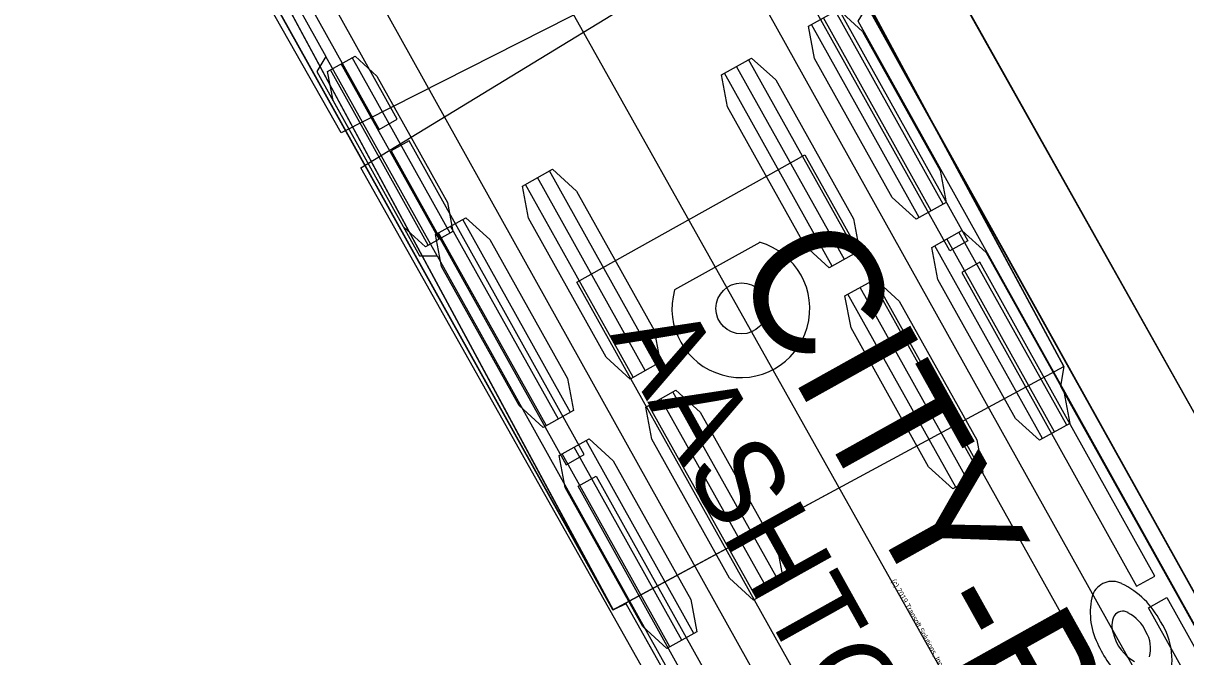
# Model space of a CAD drawing. Extents: x 1639988 to 1641860, y 841974 to 844187.
# Drawn here: x 1640568.27 to 1640587.55, y 843385.15 to 843395.66 of the extents above; entities that cross this region are included whole.
import ezdxf

# ---------------------------------------------------------------- set-up
doc = ezdxf.new("R2010")
doc.units = 0
for name, color, linetype in [('Scratch_Level_1', 7, 'Continuous'), ('Scratch_Level_2', 7, 'Continuous'), ('Scratch_Level_3', 7, 'Continuous'), ('Scratch_Level_4', 7, 'Continuous'), ('Scratch_Level_5', 7, 'Continuous'), ('Scratch_Level_6', 7, 'Continuous')]:
    doc.layers.add(name, color=color, linetype=linetype)

msp = doc.modelspace()

# ---------------------------------------------------------------- linework, layer by layer
at = {"layer": 'Scratch_Level_1'}
for p, q in [((1640561.019, 843424.987), (1640589.875, 843373.561)), ((1640583.328, 843392.545), (1640581.54, 843395.746)), ((1640583.528, 843392.657), (1640581.74, 843395.858)), ((1640583.128, 843392.433), (1640581.34, 843395.635)), ((1640581.888, 843391.741), (1640580.1, 843394.942)), ((1640582.088, 843391.852), (1640580.3, 843395.054)), ((1640581.688, 843391.629), (1640579.9, 843394.83)), ((1640578.785, 843390.007), (1640576.997, 843393.209)), ((1640578.585, 843389.896), (1640576.797, 843393.097)), ((1640578.385, 843389.784), (1640576.597, 843392.985)), ((1640577.144, 843389.091), (1640575.356, 843392.292)), ((1640577.344, 843389.203), (1640575.556, 843392.404)), ((1640576.944, 843388.979), (1640575.156, 843392.181)), ((1640585.376, 843388.878), (1640583.588, 843392.08)), ((1640585.576, 843388.99), (1640583.788, 843392.191)), ((1640580.483, 843392.023), (1640579.072, 843391.235)), ((1640585.176, 843388.767), (1640583.388, 843391.968)), ((1640583.936, 843388.074), (1640582.148, 843391.275)), ((1640584.136, 843388.186), (1640582.348, 843391.387)), ((1640583.736, 843387.962), (1640581.948, 843391.163)), ((1640580.833, 843386.341), (1640579.045, 843389.542)), ((1640580.633, 843386.229), (1640578.845, 843389.43)), ((1640580.433, 843386.117), (1640578.645, 843389.318)), ((1640579.192, 843385.424), (1640577.404, 843388.626)), ((1640579.392, 843385.536), (1640577.604, 843388.737)), ((1640578.992, 843385.313), (1640577.204, 843388.514))]:
    msp.add_line(p, q, dxfattribs=at)
for points in [[(1640557.303, 843442.315), (1640585.531, 843389.964), (1640585.474, 843389.635), (1640595.318, 843372.019), (1640588.329, 843368.125), (1640578.269, 843386.026), (1640578.051, 843385.927), (1640567.623, 843404.617), (1640561.145, 843416.327), (1640558.494, 843420.979), (1640555.889, 843425.657), (1640554.452, 843428.305), (1640561.33, 843432.392), (1640554.136, 843428.893), (1640551.649, 843433.615), (1640549.228, 843438.375), (1640546.875, 843443.171)], [(1640629.14, 843315.333), (1640571.712, 843417.686), (1640569.11, 843422.364), (1640566.534, 843427.059), (1640563.994, 843431.777), (1640560.226, 843438.882)], [(1640552.934, 843432.517), (1640552.915, 843432.507), (1640552.949, 843432.445), (1640555.639, 843427.457), (1640578.051, 843385.927), (1640581.791, 843387.945), (1640585.531, 843389.964), (1640563.12, 843431.494), (1640560.428, 843436.481), (1640560.394, 843436.543), (1640560.375, 843436.533)], [(1640582.021, 843381.774), (1640582.62, 843382.108), (1640582.505, 843382.316), (1640577.452, 843391.363), (1640579.342, 843392.419), (1640581.232, 843393.475), (1640586.285, 843384.428), (1640586.402, 843384.221), (1640587.001, 843384.555)]]:
    msp.add_lwpolyline(points, dxfattribs=at)
for points in [[(1640583.578, 843392.685), (1640583.078, 843392.406), (1640582.678, 843392.77), (1640581.39, 843395.075), (1640581.291, 843395.607), (1640581.79, 843395.886), (1640582.191, 843395.522), (1640583.478, 843393.217)], [(1640582.137, 843391.88), (1640581.638, 843391.601), (1640581.237, 843391.965), (1640579.95, 843394.27), (1640579.85, 843394.802), (1640580.349, 843395.081), (1640580.75, 843394.717), (1640582.037, 843392.412)], [(1640578.834, 843390.035), (1640578.335, 843389.756), (1640577.934, 843390.12), (1640576.647, 843392.425), (1640576.547, 843392.957), (1640577.046, 843393.236), (1640577.447, 843392.872), (1640578.734, 843390.567)], [(1640577.394, 843389.231), (1640576.894, 843388.952), (1640576.494, 843389.316), (1640575.206, 843391.621), (1640575.106, 843392.153), (1640575.606, 843392.432), (1640576.007, 843392.068), (1640577.294, 843389.763)], [(1640585.626, 843389.018), (1640585.127, 843388.739), (1640584.726, 843389.103), (1640583.438, 843391.408), (1640583.339, 843391.94), (1640583.838, 843392.219), (1640584.239, 843391.855), (1640585.526, 843389.55)], [(1640584.185, 843388.213), (1640583.686, 843387.934), (1640583.285, 843388.298), (1640581.998, 843390.603), (1640581.898, 843391.135), (1640582.397, 843391.414), (1640582.798, 843391.05), (1640584.086, 843388.745)], [(1640580.882, 843386.368), (1640580.383, 843386.089), (1640579.982, 843386.454), (1640578.695, 843388.758), (1640578.595, 843389.291), (1640579.094, 843389.57), (1640579.495, 843389.205), (1640580.782, 843386.901)], [(1640579.442, 843385.564), (1640578.942, 843385.285), (1640578.542, 843385.649), (1640577.254, 843387.954), (1640577.154, 843388.486), (1640577.654, 843388.765), (1640578.055, 843388.401), (1640579.342, 843386.096)]]:
    msp.add_lwpolyline(points, close=True, dxfattribs=at)
msp.add_circle((1640580.182, 843390.927), 0.424, dxfattribs=at)
for centre, radius, start, end in [((1640580.171, 843390.924), 1.143, 164.1847, 74.1847), ((1640586.331, 843386.054), 0.346, 62.5774, 159.5905), ((1640585.873, 843385.086), 1.416, 27.1129, 64.1808), ((1640587.103, 843385.88), 1.136, 164.9487, 206.4695), ((1640586.506, 843385.732), 0.172, 59.4864, 146.6369), ((1640586.284, 843385.292), 0.664, 24.0886, 62.3103), ((1640586.686, 843385.665), 0.362, 153.4813, 202.5223), ((1640586.187, 843385.103), 1.136, 338.8147, 33.606), ((1640587.06, 843385.707), 0.732, 194.3586, 240.593), ((1640586.445, 843385.291), 0.522, 344.1901, 31.3542), ((1640587.679, 843386.05), 1.73, 203.0114, 227.8099)]:
    msp.add_arc(centre, radius, start, end, dxfattribs=at)
at = {"layer": 'Scratch_Level_2'}
for p, q in [((1640561.019, 843424.987), (1640589.875, 843373.561)), ((1640583.328, 843392.545), (1640581.54, 843395.746)), ((1640583.528, 843392.657), (1640581.74, 843395.858)), ((1640583.128, 843392.433), (1640581.34, 843395.635)), ((1640581.888, 843391.741), (1640580.1, 843394.942)), ((1640582.088, 843391.852), (1640580.3, 843395.054)), ((1640581.688, 843391.629), (1640579.9, 843394.83)), ((1640578.785, 843390.007), (1640576.997, 843393.209)), ((1640578.585, 843389.896), (1640576.797, 843393.097)), ((1640578.385, 843389.784), (1640576.597, 843392.985)), ((1640577.144, 843389.091), (1640575.356, 843392.292)), ((1640577.344, 843389.203), (1640575.556, 843392.404)), ((1640576.944, 843388.979), (1640575.156, 843392.181)), ((1640585.376, 843388.878), (1640583.588, 843392.08)), ((1640585.576, 843388.99), (1640583.788, 843392.191)), ((1640580.483, 843392.023), (1640579.072, 843391.235)), ((1640585.176, 843388.767), (1640583.388, 843391.968)), ((1640583.936, 843388.074), (1640582.148, 843391.275)), ((1640584.136, 843388.186), (1640582.348, 843391.387)), ((1640583.736, 843387.962), (1640581.948, 843391.163)), ((1640580.833, 843386.341), (1640579.045, 843389.542)), ((1640580.633, 843386.229), (1640578.845, 843389.43)), ((1640580.433, 843386.117), (1640578.645, 843389.318)), ((1640579.192, 843385.424), (1640577.404, 843388.626)), ((1640579.392, 843385.536), (1640577.604, 843388.737)), ((1640578.992, 843385.313), (1640577.204, 843388.514))]:
    msp.add_line(p, q, dxfattribs=at)
for points in [[(1640557.951, 843441.151), (1640585.531, 843389.961), (1640585.474, 843389.635), (1640595.318, 843372.019), (1640588.329, 843368.125), (1640578.268, 843386.026), (1640578.049, 843385.928), (1640567.621, 843404.618), (1640561.144, 843416.329), (1640558.493, 843420.981), (1640555.888, 843425.659), (1640554.451, 843428.306), (1640561.331, 843432.39), (1640554.135, 843428.895), (1640551.648, 843433.617), (1640549.227, 843438.377), (1640546.874, 843443.173)], [(1640629.144, 843315.327), (1640571.712, 843417.686), (1640569.11, 843422.364), (1640566.534, 843427.059), (1640563.994, 843431.777), (1640560.226, 843438.882)], [(1640552.951, 843432.529), (1640552.932, 843432.518), (1640552.966, 843432.456), (1640555.654, 843427.467), (1640578.049, 843385.928), (1640581.79, 843387.945), (1640585.531, 843389.961), (1640563.136, 843431.501), (1640560.446, 843436.489), (1640560.413, 843436.551), (1640560.394, 843436.541)], [(1640582.021, 843381.774), (1640582.62, 843382.108), (1640582.505, 843382.316), (1640577.452, 843391.363), (1640579.342, 843392.419), (1640581.232, 843393.475), (1640586.285, 843384.428), (1640586.402, 843384.221), (1640587.001, 843384.555)]]:
    msp.add_lwpolyline(points, dxfattribs=at)
for points in [[(1640583.578, 843392.685), (1640583.078, 843392.406), (1640582.678, 843392.77), (1640581.39, 843395.075), (1640581.291, 843395.607), (1640581.79, 843395.886), (1640582.191, 843395.522), (1640583.478, 843393.217)], [(1640582.137, 843391.88), (1640581.638, 843391.601), (1640581.237, 843391.965), (1640579.95, 843394.27), (1640579.85, 843394.802), (1640580.349, 843395.081), (1640580.75, 843394.717), (1640582.037, 843392.412)], [(1640578.834, 843390.035), (1640578.335, 843389.756), (1640577.934, 843390.12), (1640576.647, 843392.425), (1640576.547, 843392.957), (1640577.046, 843393.236), (1640577.447, 843392.872), (1640578.734, 843390.567)], [(1640577.394, 843389.231), (1640576.894, 843388.952), (1640576.494, 843389.316), (1640575.206, 843391.621), (1640575.106, 843392.153), (1640575.606, 843392.432), (1640576.007, 843392.068), (1640577.294, 843389.763)], [(1640585.626, 843389.018), (1640585.127, 843388.739), (1640584.726, 843389.103), (1640583.438, 843391.408), (1640583.339, 843391.94), (1640583.838, 843392.219), (1640584.239, 843391.855), (1640585.526, 843389.55)], [(1640584.185, 843388.213), (1640583.686, 843387.934), (1640583.285, 843388.298), (1640581.998, 843390.603), (1640581.898, 843391.135), (1640582.397, 843391.414), (1640582.798, 843391.05), (1640584.086, 843388.745)], [(1640580.882, 843386.368), (1640580.383, 843386.089), (1640579.982, 843386.454), (1640578.695, 843388.758), (1640578.595, 843389.291), (1640579.094, 843389.57), (1640579.495, 843389.205), (1640580.782, 843386.901)], [(1640579.442, 843385.564), (1640578.942, 843385.285), (1640578.542, 843385.649), (1640577.254, 843387.954), (1640577.154, 843388.486), (1640577.654, 843388.765), (1640578.055, 843388.401), (1640579.342, 843386.096)]]:
    msp.add_lwpolyline(points, close=True, dxfattribs=at)
msp.add_circle((1640580.182, 843390.927), 0.424, dxfattribs=at)
for centre, radius, start, end in [((1640580.171, 843390.924), 1.143, 164.1847, 74.1847), ((1640586.331, 843386.054), 0.346, 62.5774, 159.5905), ((1640585.873, 843385.086), 1.416, 27.1129, 64.1808), ((1640587.103, 843385.88), 1.136, 164.9487, 206.4695), ((1640586.506, 843385.732), 0.172, 59.4864, 146.6369), ((1640586.284, 843385.292), 0.664, 24.0886, 62.3103), ((1640586.686, 843385.665), 0.362, 153.4813, 202.5223), ((1640586.187, 843385.103), 1.136, 338.8147, 33.606), ((1640587.06, 843385.707), 0.732, 194.3586, 240.593), ((1640586.445, 843385.291), 0.522, 344.1901, 31.3542), ((1640587.679, 843386.05), 1.73, 203.0114, 227.8099)]:
    msp.add_arc(centre, radius, start, end, dxfattribs=at)
at = {"layer": 'Scratch_Level_3'}
for p, q in [((1640561.019, 843424.987), (1640589.875, 843373.561)), ((1640583.328, 843392.545), (1640581.54, 843395.746)), ((1640583.528, 843392.657), (1640581.74, 843395.858)), ((1640583.128, 843392.433), (1640581.34, 843395.635)), ((1640581.888, 843391.741), (1640580.1, 843394.942)), ((1640582.088, 843391.852), (1640580.3, 843395.054)), ((1640581.688, 843391.629), (1640579.9, 843394.83)), ((1640578.785, 843390.007), (1640576.997, 843393.209)), ((1640578.585, 843389.896), (1640576.797, 843393.097)), ((1640578.385, 843389.784), (1640576.597, 843392.985)), ((1640577.144, 843389.091), (1640575.356, 843392.292)), ((1640577.344, 843389.203), (1640575.556, 843392.404)), ((1640576.944, 843388.979), (1640575.156, 843392.181)), ((1640585.376, 843388.878), (1640583.588, 843392.08)), ((1640585.576, 843388.99), (1640583.788, 843392.191)), ((1640580.483, 843392.023), (1640579.072, 843391.235)), ((1640585.176, 843388.767), (1640583.388, 843391.968)), ((1640583.936, 843388.074), (1640582.148, 843391.275)), ((1640584.136, 843388.186), (1640582.348, 843391.387)), ((1640583.736, 843387.962), (1640581.948, 843391.163)), ((1640580.833, 843386.341), (1640579.045, 843389.542)), ((1640580.633, 843386.229), (1640578.845, 843389.43)), ((1640580.433, 843386.117), (1640578.645, 843389.318)), ((1640579.192, 843385.424), (1640577.404, 843388.626)), ((1640579.392, 843385.536), (1640577.604, 843388.737)), ((1640578.992, 843385.313), (1640577.204, 843388.514))]:
    msp.add_line(p, q, dxfattribs=at)
for points in [[(1640556.856, 843443.205), (1640561.886, 843433.823), (1640585.531, 843389.961), (1640585.474, 843389.635), (1640595.318, 843372.019), (1640588.331, 843368.123), (1640578.268, 843386.026), (1640578.049, 843385.928), (1640567.621, 843404.618), (1640561.144, 843416.329), (1640558.493, 843420.981), (1640555.888, 843425.659), (1640554.451, 843428.306), (1640561.331, 843432.39), (1640554.135, 843428.895), (1640551.648, 843433.617), (1640549.227, 843438.377), (1640546.874, 843443.174)], [(1640629.149, 843315.318), (1640571.712, 843417.686), (1640569.11, 843422.364), (1640566.534, 843427.059), (1640563.994, 843431.777), (1640560.226, 843438.882)], [(1640552.953, 843432.529), (1640552.933, 843432.519), (1640552.967, 843432.457), (1640555.656, 843427.468), (1640578.049, 843385.928), (1640581.79, 843387.945), (1640585.531, 843389.961), (1640563.138, 843431.501), (1640560.448, 843436.49), (1640560.414, 843436.552), (1640560.395, 843436.542)], [(1640582.021, 843381.774), (1640582.62, 843382.108), (1640582.505, 843382.316), (1640577.452, 843391.363), (1640579.342, 843392.419), (1640581.232, 843393.475), (1640586.285, 843384.428), (1640586.402, 843384.221), (1640587.001, 843384.555)]]:
    msp.add_lwpolyline(points, dxfattribs=at)
for points in [[(1640583.578, 843392.685), (1640583.078, 843392.406), (1640582.678, 843392.77), (1640581.39, 843395.075), (1640581.291, 843395.607), (1640581.79, 843395.886), (1640582.191, 843395.522), (1640583.478, 843393.217)], [(1640582.137, 843391.88), (1640581.638, 843391.601), (1640581.237, 843391.965), (1640579.95, 843394.27), (1640579.85, 843394.802), (1640580.349, 843395.081), (1640580.75, 843394.717), (1640582.037, 843392.412)], [(1640578.834, 843390.035), (1640578.335, 843389.756), (1640577.934, 843390.12), (1640576.647, 843392.425), (1640576.547, 843392.957), (1640577.046, 843393.236), (1640577.447, 843392.872), (1640578.734, 843390.567)], [(1640577.394, 843389.231), (1640576.894, 843388.952), (1640576.494, 843389.316), (1640575.206, 843391.621), (1640575.106, 843392.153), (1640575.606, 843392.432), (1640576.007, 843392.068), (1640577.294, 843389.763)], [(1640585.626, 843389.018), (1640585.127, 843388.739), (1640584.726, 843389.103), (1640583.438, 843391.408), (1640583.339, 843391.94), (1640583.838, 843392.219), (1640584.239, 843391.855), (1640585.526, 843389.55)], [(1640584.185, 843388.213), (1640583.686, 843387.934), (1640583.285, 843388.298), (1640581.998, 843390.603), (1640581.898, 843391.135), (1640582.397, 843391.414), (1640582.798, 843391.05), (1640584.086, 843388.745)], [(1640580.882, 843386.368), (1640580.383, 843386.089), (1640579.982, 843386.454), (1640578.695, 843388.758), (1640578.595, 843389.291), (1640579.094, 843389.57), (1640579.495, 843389.205), (1640580.782, 843386.901)], [(1640579.442, 843385.564), (1640578.942, 843385.285), (1640578.542, 843385.649), (1640577.254, 843387.954), (1640577.154, 843388.486), (1640577.654, 843388.765), (1640578.055, 843388.401), (1640579.342, 843386.096)]]:
    msp.add_lwpolyline(points, close=True, dxfattribs=at)
msp.add_circle((1640580.182, 843390.927), 0.424, dxfattribs=at)
for centre, radius, start, end in [((1640580.171, 843390.924), 1.143, 164.1847, 74.1847), ((1640586.331, 843386.054), 0.346, 62.5774, 159.5905), ((1640585.873, 843385.086), 1.416, 27.1129, 64.1808), ((1640587.103, 843385.88), 1.136, 164.9487, 206.4695), ((1640586.506, 843385.732), 0.172, 59.4864, 146.6369), ((1640586.284, 843385.292), 0.664, 24.0886, 62.3103), ((1640586.686, 843385.665), 0.362, 153.4813, 202.5223), ((1640586.187, 843385.103), 1.136, 338.8147, 33.606), ((1640587.06, 843385.707), 0.732, 194.3586, 240.593), ((1640586.445, 843385.291), 0.522, 344.1901, 31.3542), ((1640587.679, 843386.05), 1.73, 203.0114, 227.8099)]:
    msp.add_arc(centre, radius, start, end, dxfattribs=at)
at = {"layer": 'Scratch_Level_4'}
for p, q in [((1640561.019, 843424.987), (1640589.875, 843373.561)), ((1640594.695, 843370.601), (1640576.956, 843402.423)), ((1640572.119, 843399.726), (1640589.858, 843367.905)), ((1640575.131, 843391.797), (1640573.288, 843395.104)), ((1640575.166, 843392.075), (1640573.543, 843394.987)), ((1640575.348, 843392.176), (1640573.725, 843395.088)), ((1640574.984, 843391.974), (1640573.361, 843394.885))]:
    msp.add_line(p, q, dxfattribs=at)
for points in [[(1640558.794, 843438.559), (1640563.861, 843429.211), (1640568.98, 843419.88), (1640574.133, 843410.56), (1640596.995, 843369.516), (1640589.571, 843365.377), (1640573.868, 843393.261), (1640581.129, 843397.688), (1640573.54, 843393.841), (1640559.056, 843419.365), (1640557.759, 843421.699), (1640556.481, 843424.044), (1640555.22, 843426.399), (1640553.978, 843428.764), (1640544.238, 843447.821)], [(1640611.208, 843347.292), (1640590.328, 843384.504), (1640574.652, 843412.392), (1640569.434, 843421.74), (1640561.561, 843435.788), (1640560.271, 843438.147), (1640559.001, 843440.517)], [(1640595.769, 843371.2), (1640594.368, 843373.714), (1640594.439, 843374.102), (1640592.735, 843377.159), (1640592.368, 843377.302), (1640582.117, 843395.691), (1640582.267, 843395.938), (1640580.562, 843398.995), (1640580.273, 843398.998), (1640578.03, 843403.022)], [(1640571.045, 843399.128), (1640573.288, 843395.104), (1640573.138, 843394.856), (1640574.842, 843391.799), (1640575.131, 843391.797), (1640585.382, 843373.408), (1640585.311, 843373.02), (1640587.015, 843369.963), (1640587.382, 843369.82)]]:
    msp.add_lwpolyline(points, dxfattribs=at)
for points in [[(1640571.57, 843399.27), (1640571.269, 843399.102), (1640574.171, 843393.896), (1640574.472, 843394.065)], [(1640580.734, 843397.087), (1640581.035, 843397.255), (1640583.937, 843392.049), (1640583.635, 843391.882)], [(1640575.393, 843392.202), (1640574.938, 843391.948), (1640574.574, 843392.28), (1640573.406, 843394.376), (1640573.315, 843394.86), (1640573.77, 843395.113), (1640574.134, 843394.782), (1640575.302, 843392.685)], [(1640574.671, 843393.707), (1640574.37, 843393.539), (1640577.272, 843388.334), (1640577.572, 843388.503)], [(1640586.736, 843386.32), (1640587.037, 843386.488), (1640584.136, 843391.692), (1640583.834, 843391.524)], [(1640580.673, 843382.94), (1640580.372, 843382.772), (1640577.47, 843387.977), (1640577.772, 843388.145)], [(1640586.935, 843385.962), (1640587.237, 843386.13), (1640590.138, 843380.924), (1640589.837, 843380.757)]]:
    msp.add_lwpolyline(points, close=True, dxfattribs=at)
at = {"layer": 'Scratch_Level_5'}
for p, q in [((1640561.019, 843424.987), (1640589.875, 843373.561)), ((1640594.695, 843370.601), (1640576.956, 843402.423)), ((1640572.119, 843399.726), (1640589.858, 843367.905)), ((1640575.131, 843391.797), (1640573.288, 843395.104)), ((1640575.166, 843392.075), (1640573.543, 843394.987)), ((1640575.348, 843392.176), (1640573.725, 843395.088)), ((1640574.984, 843391.974), (1640573.361, 843394.885))]:
    msp.add_line(p, q, dxfattribs=at)
for points in [[(1640558.636, 843438.852), (1640563.702, 843429.503), (1640568.819, 843420.171), (1640573.971, 843410.851), (1640596.995, 843369.516), (1640589.571, 843365.377), (1640573.868, 843393.261), (1640581.129, 843397.688), (1640573.54, 843393.841), (1640559.056, 843419.365), (1640557.759, 843421.699), (1640556.481, 843424.044), (1640555.22, 843426.399), (1640553.978, 843428.764), (1640544.238, 843447.821)], [(1640611.214, 843347.281), (1640590.328, 843384.504), (1640574.652, 843412.392), (1640569.434, 843421.74), (1640561.561, 843435.788), (1640560.271, 843438.147), (1640559.001, 843440.517)], [(1640595.769, 843371.2), (1640594.368, 843373.714), (1640594.439, 843374.102), (1640592.735, 843377.159), (1640592.368, 843377.302), (1640582.117, 843395.691), (1640582.267, 843395.938), (1640580.562, 843398.995), (1640580.273, 843398.998), (1640578.03, 843403.022)], [(1640571.045, 843399.128), (1640573.288, 843395.104), (1640573.138, 843394.856), (1640574.842, 843391.799), (1640575.131, 843391.797), (1640585.382, 843373.408), (1640585.311, 843373.02), (1640587.015, 843369.963), (1640587.382, 843369.82)]]:
    msp.add_lwpolyline(points, dxfattribs=at)
for points in [[(1640571.57, 843399.27), (1640571.269, 843399.102), (1640574.171, 843393.896), (1640574.472, 843394.065)], [(1640580.734, 843397.087), (1640581.035, 843397.255), (1640583.937, 843392.049), (1640583.635, 843391.882)], [(1640575.393, 843392.202), (1640574.938, 843391.948), (1640574.574, 843392.28), (1640573.406, 843394.376), (1640573.315, 843394.86), (1640573.77, 843395.113), (1640574.134, 843394.782), (1640575.302, 843392.685)], [(1640574.671, 843393.707), (1640574.37, 843393.539), (1640577.272, 843388.334), (1640577.572, 843388.503)], [(1640586.736, 843386.32), (1640587.037, 843386.488), (1640584.136, 843391.692), (1640583.834, 843391.524)], [(1640580.673, 843382.94), (1640580.372, 843382.772), (1640577.47, 843387.977), (1640577.772, 843388.145)], [(1640586.935, 843385.962), (1640587.237, 843386.13), (1640590.138, 843380.924), (1640589.837, 843380.757)]]:
    msp.add_lwpolyline(points, close=True, dxfattribs=at)
at = {"layer": 'Scratch_Level_6'}
for p, q in [((1640561.019, 843424.987), (1640589.875, 843373.561)), ((1640594.695, 843370.601), (1640576.956, 843402.423)), ((1640572.119, 843399.726), (1640589.858, 843367.905)), ((1640575.131, 843391.797), (1640573.288, 843395.104)), ((1640575.166, 843392.075), (1640573.543, 843394.987)), ((1640575.348, 843392.176), (1640573.725, 843395.088)), ((1640574.984, 843391.974), (1640573.361, 843394.885))]:
    msp.add_line(p, q, dxfattribs=at)
for points in [[(1640557.068, 843441.778), (1640562.112, 843432.422), (1640567.216, 843423.086), (1640572.358, 843413.763), (1640582.875, 843394.846), (1640596.995, 843369.516), (1640589.571, 843365.377), (1640573.868, 843393.261), (1640581.129, 843397.688), (1640573.54, 843393.841), (1640559.056, 843419.365), (1640557.759, 843421.699), (1640556.481, 843424.044), (1640555.22, 843426.399), (1640553.978, 843428.764), (1640544.238, 843447.821)], [(1640611.238, 843347.239), (1640590.328, 843384.504), (1640574.652, 843412.392), (1640569.434, 843421.74), (1640561.561, 843435.788), (1640560.271, 843438.147), (1640559.001, 843440.517)], [(1640595.769, 843371.2), (1640594.368, 843373.714), (1640594.439, 843374.102), (1640592.735, 843377.159), (1640592.368, 843377.302), (1640582.117, 843395.691), (1640582.267, 843395.938), (1640580.562, 843398.995), (1640580.273, 843398.998), (1640578.03, 843403.022)], [(1640571.045, 843399.128), (1640573.288, 843395.104), (1640573.138, 843394.856), (1640574.842, 843391.799), (1640575.131, 843391.797), (1640585.382, 843373.408), (1640585.311, 843373.02), (1640587.015, 843369.963), (1640587.382, 843369.82)]]:
    msp.add_lwpolyline(points, dxfattribs=at)
for points in [[(1640571.57, 843399.27), (1640571.269, 843399.102), (1640574.171, 843393.896), (1640574.472, 843394.065)], [(1640580.734, 843397.087), (1640581.035, 843397.255), (1640583.937, 843392.049), (1640583.635, 843391.882)], [(1640575.393, 843392.202), (1640574.938, 843391.948), (1640574.574, 843392.28), (1640573.406, 843394.376), (1640573.315, 843394.86), (1640573.77, 843395.113), (1640574.134, 843394.782), (1640575.302, 843392.685)], [(1640574.671, 843393.707), (1640574.37, 843393.539), (1640577.272, 843388.334), (1640577.572, 843388.503)], [(1640586.736, 843386.32), (1640587.037, 843386.488), (1640584.136, 843391.692), (1640583.834, 843391.524)], [(1640580.673, 843382.94), (1640580.372, 843382.772), (1640577.47, 843387.977), (1640577.772, 843388.145)], [(1640586.935, 843385.962), (1640587.237, 843386.13), (1640590.138, 843380.924), (1640589.837, 843380.757)]]:
    msp.add_lwpolyline(points, close=True, dxfattribs=at)

# ---------------------------------------------------------------- texts
at = {"layer": 'Scratch_Level_4'}
for s, height, p in [('CITY-BUS', 2.125, (1640579.998, 843391.627)), ('AASHTO 2011 (US)', 1.41667, (1640578, 843390.484)), ('(c) 2019 Transoft Solutions, Inc. All rights reserved.', 0.085, (1640582.665, 843386.408))]:
    msp.add_text(s, height=height, rotation=299.1372, dxfattribs=at).set_placement(p)
at = {"layer": 'Scratch_Level_5'}
for s, height, p in [('CITY-BUS', 2.125, (1640579.998, 843391.627)), ('AASHTO 2011 (US)', 1.41667, (1640578, 843390.484)), ('(c) 2019 Transoft Solutions, Inc. All rights reserved.', 0.085, (1640582.665, 843386.408))]:
    msp.add_text(s, height=height, rotation=299.1372, dxfattribs=at).set_placement(p)
at = {"layer": 'Scratch_Level_6'}
for s, height, p in [('CITY-BUS', 2.125, (1640579.998, 843391.627)), ('AASHTO 2011 (US)', 1.41667, (1640578, 843390.484)), ('(c) 2019 Transoft Solutions, Inc. All rights reserved.', 0.085, (1640582.665, 843386.408))]:
    msp.add_text(s, height=height, rotation=299.1372, dxfattribs=at).set_placement(p)

doc.saveas('drawing.dxf')
